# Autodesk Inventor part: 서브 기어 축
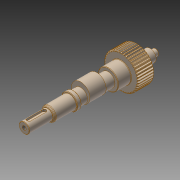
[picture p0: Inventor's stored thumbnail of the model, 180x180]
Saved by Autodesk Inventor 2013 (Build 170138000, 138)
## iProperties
Created: 2018-12
Part Number: 서브 기어 축
Material: 강철, 연강
Document SubType Name: Modeling
Designer: mduedu
Categories: <?xml version="1.0" encoding="UTF-16"?> <MemberInstance><Categories><FamilyTemplate><FamilyTemplateParameter ValueType="xs:double" Id="1" ObjectReferenceKey="da
Density: 7.86 g/cm^3
Mass: 484.999 g
Surface Area: 155.104 cm^2
Volume: 61.7047 cm^3
Author: mduedu
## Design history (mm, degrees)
sketch "Sketch1"
  geometry: C1 r 21.3 at (0, 0)
  constraints: 1 centre point
  dimensions: "d0" = 42.6 diameter of C1 (= da_da)
extrude "Extrusion1" new body sketch "Sketch1" distance "d1" = 20 (= da_b); taper "d2" = 0 deg
workplane "Work Plane2"
sketch "Sketch2"
  geometry: C1 r 21.3 at (0, 0) reference; C2 r 20.5 at (0, 0)
  constraints: 1 centre point, 1 coincident
  dimensions: "d3" = 41 diameter of C2 (= da_dw)
feature "피치 지름" sketch "Sketch2" dims "d4" = 10, "d5" = 0
workplane "Work Plane8"
workplane "Work Plane9"
chamfer "모따기1" distance "d49" = 1; stored, may be unused: second distance "d50" = 2, angle "d51" = 45 deg
sketch "스케치3"
  geometry: C1 r 12.5 at (0, 0); 1 further point
  constraints: 1 centre point, 1 coincident
  dimensions: "d52" = 25 diameter of C1
extrude "돌출2" join sketch "스케치3" distance "d53" = 16; taper "d54" = 0 deg
sketch "스케치4"
  geometry: C1 r 8.5 at (0, 0); 1 further point
  constraints: 1 centre point, 1 coincident
  dimensions: "d55" = 17 diameter of C1
extrude "돌출3" join sketch "스케치4" distance "d56" = 104; taper "d57" = 0 deg
sketch "스케치5"
  geometry: C1 r 7.5 at (0, 0); 1 further point
  constraints: 1 centre point, 1 coincident
  dimensions: "d58" = 15 diameter of C1
extrude "돌출4" join sketch "스케치5" distance "d59" = 16; taper "d60" = 0 deg
sketch "스케치6"
  geometry: C1 r 4 at (0, 0); 1 further point
  constraints: 1 centre point, 1 coincident
  dimensions: "d61" = 8 diameter of C1
extrude "돌출5" join sketch "스케치6" distance "d62" = 7; taper "d63" = 0 deg
fillet "모깎기1" dims "d67" = 0.5
feature "스퍼 기어" dims "da_b" = 20, "da_d" = 41, "da_aw" = 31, "da_da" = 42.6, "da_df" = 39.086, "da_dw" = 41, angle "da_beta" = 0 deg, "da_lefttooth" = 0, "da_righttooth" = 0
node "작업 평면11"
sketch "스케치7"
  geometry: C1 r 11.5 at (0, 3); C2 r 8.5 at (0, 0) reference; 1 further point
  constraints: 1 centre point, 1 tangent, 1 vertical alignment
  dimensions: "d69" = 3 distance of point (0, 0) C1.centre; "d70" = 23 diameter of C1 (derived)
extrude "돌출6" join sketch "스케치7" stored distance "d71" = 20; taper "d72" = 0 deg
node "작업 평면12"
sketch "스케치8"
  geometry: C1 r 12.5 at (0, 0) reference; C2 r 10 at (0, 0); 1 further point
  constraints: 1 centre point, 1 coincident
  dimensions: "d110" = 20 diameter of C2
extrude "돌출7" join sketch "스케치8" distance "d74" = 5; taper "d75" = 0 deg
sketch "스케치14"
  geometry: L1 (-11.5, 111)-(-6.5, 111); L2 (-6.5, 111)-(-6.5, 140); L3 (-6.5, 140)-(-11.5, 140); L4 (-11.5, 140)-(-11.5, 111); L5 (8.5, 140)-(-8.5, 140) reference; L6 (0, 0)-(0, 140)
  constraints: 10 end point, 2 parallel, 1 collinear, 1 horizontal, 1 midpoint, 1 perpendicular
  dimensions: "d92" = 29 distance between parallel lines of L1 L5; "d93" = 13 diameter of L2 L6; "d95" = 5 distance of L2.end L3.end
revolve "회전2" sketch "스케치14" stored, may be unused: angle "d96" = 90 deg
chamfer "모따기4" distance "d97" = 0.5; stored, may be unused: second distance "d98" = 2, angle "d99" = 45 deg
node "작업 평면13"
sketch "스케치11"
  geometry: L1 (-2.5, 9)-(-2.5, -10); L2 (2.5, -10)-(2.5, 9); L3 (-6, 14.5)-(6, 14.5) reference; A1 r 2.5 centre (0, 9) between (2.5, 9) and (-2.5, 9); A2 r 2.5 centre (0, -10) between (-2.5, -10) and (2.5, -10); 1 further point
  constraints: 4 end point, 4 point on circle, 4 tangent, 2 centre point, 2 vertical alignment, 1 parallel
  dimensions: "d84" = 24 dimension on A2 A1; "d85" = 5 distance between parallel lines of L1 L2; "d108" = 3 distance edge to line of A1 L3
extrude "돌출8" cut sketch "스케치11" distance "d86" = 3; taper "d87" = 0 deg
sketch "스케치12" dims "d88" = 32
  geometry: C1 r 0.5 at (0, -16); 2 further points
  constraints: 2 vertical alignment, 1 centre point, 1 coincident, 2 other
  dimensions: "d89" = 1 diameter of C1
extrude "돌출9" join sketch "스케치12" distance "d90" = 0.3; taper "d91" = 0 deg
sketch "스케치13"
  geometry: C1 r 11.5 at (0, 3) reference; 1 further point
  node "절단 모서리 투영1"
sketch "스케치15"
  geometry: L1 (-8.5, 109.181)-(-7.45, 111); L2 (-8.5, 111)-(8.5, 111) reference; L3 (-8.5, 84)-(-8.5, 111) reference; L4 (0, 0)-(0, 111); L5 (-7.45, 111)-(-8.5, 111); L6 (-8.5, 109.181)-(-8.5, 111)
  constraints: 8 end point, 2 collinear, 2 point on line, 1 midpoint
  dimensions: "d103" = 14.9 diameter of L1.end L4; "d104" = 30 deg angle of L3 L1
revolve "회전3" sketch "스케치15" stored, may be unused: angle "d105" = 90 deg
fillet "모깎기2" dims "d106" = 2
fillet "모깎기3" dims "d107" = 1
chamfer "모따기5" distance "d112" = 0.5; stored, may be unused: second distance "d113" = 2, angle "d114" = 45 deg
hole "구멍1" diameter "d117" = 4.917; stored, may be unused: countersink angle "d121" = 90 deg, drill point angle "d123" = 118 deg; dims "d118" = 12, "d119" = 4, "d120" = 2, "d122" = 14, "d124" = 10, "d125" = 10
body "Solid1"
body "Srf1"
node "투영된 루프1"
other parameters: "d16" = 31 (= da_aw), "d17" = 0, "d34" = 0.76624 (computed from da_z), "d39" = 0, "d41" = 0, "d43" = 31 (= da_aw), "d46" = 31 (= da_aw), "d47" = 0, "d48" = 0
